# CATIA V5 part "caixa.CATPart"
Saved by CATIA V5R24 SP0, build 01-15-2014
Part number: caixa
Bounding box of the stored display mesh (mm): x 0 to 47, y -60 to 60, z -110 to 110
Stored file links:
  C:\Users\Fatec\Desktop\Maquina componentes catia\caixa.CATPart
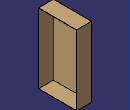
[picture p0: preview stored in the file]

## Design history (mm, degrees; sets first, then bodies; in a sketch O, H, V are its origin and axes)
Body1 (main body)
  Sketch1 on yz-plane, origin (0, 0, 0), H (0, 1, 0), V (0, 0, 1)
    line L1 (-60, 110) -> (60, 110)
    line L2 (60, 110) -> (60, -110)
    line L3 (60, -110) -> (-60, -110)
    line L4 (-60, -110) -> (-60, 110)
    length L3 = 120
    length L2 = 220
    horizontal: L1 H, L3 H
    vertical: L2 V, L4 V
    symmetry: L4 L2 V, L3 L1 H
  Pad1: profile Sketch1, direction (1, 0, 0), length 47
  Sketch2 on end face of Pad1, origin (47, 0, 0), H (0, 1, 0), V (0, 0, 1)
    line L1 (-59, 109) -> (59, 109)
    line L2 (59, 109) -> (59, -109)
    line L3 (59, -109) -> (-59, -109)
    line L4 (-59, -109) -> (-59, 109)
    length L2 = 218
    length L3 = 118
    horizontal: L1 H, L3 H
    vertical: L2 V, L4 V
    symmetry: L4 L2 V, L3 L1 H
  Pocket1: profile Sketch2, direction (-1, 0, 0), length 46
